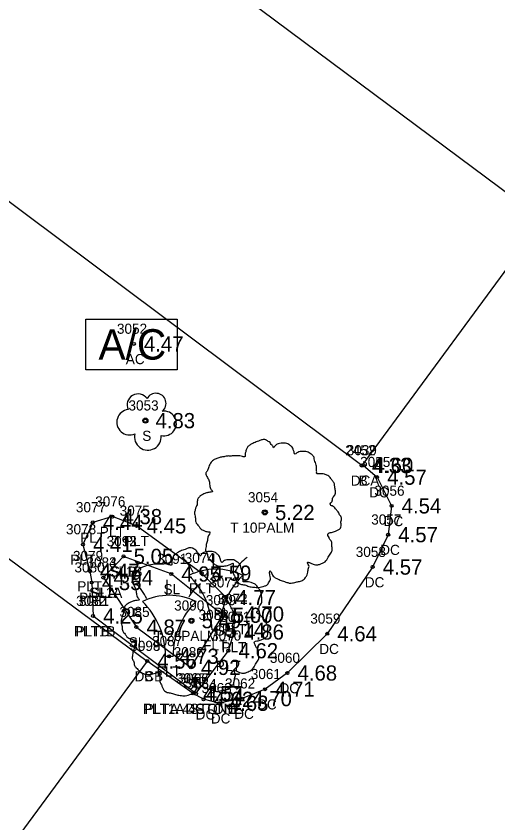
# Model space of a CAD drawing. Extents: x 2608598 to 2610682, y 641451 to 643526.
# Drawn here: x 2609965.9 to 2610013.4, y 642071.3 to 642151 of the extents above; entities that cross this region are included whole.
import ezdxf

# ---------------------------------------------------------------- set-up
doc = ezdxf.new("R2010")
doc.units = 0
for name, color, linetype in [('RD_EX_Bldg', 7, 'Continuous'), ('RD_EX_Bldg_txCode', 7, 'Continuous'), ('RD_EX_BldgApp', 7, 'Continuous'), ('RD_EX_BldgApp_txCode', 7, 'Continuous'), ('RD_EX_Conc', 7, 'Continuous'), ('RD_EX_Conc_txCode', 7, 'Continuous'), ('RD_EX_TX_Bldg_ELEV', 7, 'Continuous'), ('RD_EX_TX_BldgApp_ELEV', 7, 'Continuous'), ('RD_EX_TX_Conc_ELEV', 7, 'Continuous'), ('RD_EX_TX_VEG_ELEV', 7, 'Continuous'), ('RD_EX_VEG', 7, 'Continuous'), ('RD_EX_VEG_txCode', 7, 'Continuous'), ('RD_SMD_Locator', 7, 'Continuous')]:
    doc.layers.add(name, color=color, linetype=linetype)

msp = doc.modelspace()

# ---------------------------------------------------------------- linework, layer by layer
at = {"layer": 'RD_EX_Bldg'}
for points in [[(2609946.85, 642146.346), (2609965.057, 642170.243), (2610017.876, 642130.878), (2610000.016, 642106.607), (2609946.85, 642146.346)], [(2609925.869, 642126.537), (2609978.853, 642087.305), (2609961.016, 642063.114), (2609908.032, 642102.345), (2609925.869, 642126.537)]]:
    msp.add_lwpolyline(points, dxfattribs=at)
at = {"layer": 'RD_EX_BldgApp'}
for p, q in [((2609983.661, 642084.088), (2609973.511, 642091.75)), ((2609985.248, 642090.378), (2609985.998, 642090.378)), ((2609980.658, 642087.798), (2609981.408, 642087.798))]:
    msp.add_line(p, q, dxfattribs=at)
msp.add_lwpolyline([(2609972.804, 642116.056), (2609972.804, 642121.056), (2609981.804, 642121.056), (2609981.804, 642116.056)], close=True, dxfattribs=at)
msp.add_lwpolyline([(2609983.661, 642084.088), (2609986.863, 642088.328), (2609987.438, 642090.174), (2609987.45, 642091.947), (2609986.646, 642093.573), (2609984.226, 642095.984), (2609977.805, 642100.65), (2609975.417, 642101.56), (2609973.488, 642100.991), (2609972.51, 642098.817), (2609973.198, 642096.178), (2609973.385, 642095.054), (2609973.511, 642091.75)], dxfattribs=at)
for centre, radius, start, end in [((2609978.931, 642094.021), 4.895, 24.32791, 46.26654), ((2609947.542, 642097.716), 37.876, 358.06712, 0.27154), ((2609990.511, 642094.772), 3.283, 123.29064, 154.48862), ((2609985.623, 642090.378), 5.997, 63.77943, 116.22057), ((2609977.748, 642090.378), 7.5, 0, 45.83662), ((2609993.498, 642090.378), 7.5, 134.16338, 180), ((2609974.341, 642091.44), 4.895, 24.32791, 46.26654), ((2609942.952, 642095.135), 37.876, 358.06712, 0.27154), ((2609985.922, 642092.191), 3.283, 123.29064, 154.48862), ((2609981.033, 642087.798), 5.997, 63.77943, 116.22057), ((2609973.158, 642087.798), 7.5, 0, 45.83662), ((2609988.908, 642087.798), 7.5, 134.16338, 180)]:
    msp.add_arc(centre, radius, start, end, dxfattribs=at)
at = {"layer": 'RD_EX_Conc'}
msp.add_lwpolyline([(2610000.202, 642106.619), (2610001.534, 642105.457), (2610002.96, 642102.62), (2610002.625, 642099.778), (2610001.097, 642096.583), (2609996.612, 642089.998), (2609992.685, 642086.129), (2609990.483, 642084.529), (2609988.224, 642083.597), (2609985.911, 642083.142), (2609984.416, 642083.531), (2609983.386, 642084.107), (2609978.853, 642087.305)], dxfattribs=at)
at = {"layer": 'RD_EX_VEG'}
msp.add_line((2609974.531, 642095.545), (2609976.518, 642097.638), dxfattribs=at)
msp.add_lwpolyline([(2609974.531, 642095.545), (2609977.785, 642090.655), (2609983.161, 642086.682), (2609986.308, 642091.823), (2609981.222, 642095.898), (2609976.518, 642097.638)], dxfattribs=at)
for centre, radius in [((2609978.674, 642111.034), 0.25), ((2609990.462, 642101.972), 0.25), ((2609990.449, 642101.953), 0.0001), ((2609983.22, 642091.29), 0.25), ((2609983.208, 642091.271), 0.0001)]:
    msp.add_circle(centre, radius, dxfattribs=at)
for centre, radius, start, end in [((2609977.953, 642112.581), 1.084, 34.97629, 204.75602), ((2609979.719, 642112.736), 0.995, 308.76261, 152.04674), ((2609977.11, 642110.878), 1.257, 96.45179, 294.73401), ((2609980.514, 642110.754), 1.218, 256.56668, 98.10463), ((2609978.92, 642109.437), 1.318, 166.88266, 5.75893)]:
    msp.add_arc(centre, radius, start, end, dxfattribs=at)
for points in [[(2609990.594, 642109.139), (2609990.294, 642109.164), (2609989.969, 642109.064), (2609989.719, 642108.964), (2609989.494, 642108.889), (2609989.269, 642108.789), (2609988.97, 642108.615), (2609988.745, 642108.414), (2609988.62, 642108.165), (2609988.57, 642107.94), (2609988.52, 642107.665), (2609988.52, 642107.49), (2609988.395, 642107.465), (2609988.245, 642107.49), (2609987.995, 642107.565), (2609987.745, 642107.565), (2609987.495, 642107.565), (2609987.145, 642107.54), (2609986.795, 642107.54), (2609986.521, 642107.49), (2609986.196, 642107.44), (2609985.821, 642107.315), (2609985.471, 642107.19), (2609985.171, 642106.94), (2609984.921, 642106.465), (2609984.796, 642106.116), (2609984.646, 642105.866), (2609984.796, 642105.416), (2609984.971, 642105.066), (2609984.996, 642104.866), (2609985.071, 642104.441), (2609985.171, 642104.216), (2609985.296, 642104.016), (2609985.221, 642103.992), (2609984.846, 642103.941), (2609984.546, 642103.842), (2609984.122, 642103.617), (2609983.897, 642103.392), (2609983.797, 642103.067), (2609983.772, 642102.717), (2609983.672, 642102.517), (2609983.597, 642102.242), (2609983.572, 642102.167), (2609983.522, 642101.842), (2609983.622, 642101.393), (2609983.647, 642101.043), (2609983.772, 642100.818), (2609983.922, 642100.643), (2609984.097, 642100.393), (2609984.496, 642100.168), (2609984.821, 642100.068), (2609985.021, 642100.043), (2609984.846, 642099.543), (2609984.796, 642099.194), (2609984.671, 642098.794), (2609984.671, 642098.719), (2609984.621, 642098.244), (2609984.771, 642097.919), (2609984.846, 642097.544), (2609985.021, 642097.319), (2609985.296, 642097.02), (2609985.621, 642096.795), (2609986.121, 642096.67), (2609986.521, 642096.695), (2609987.095, 642096.87), (2609987.345, 642096.945), (2609987.32, 642096.77), (2609987.345, 642096.395), (2609987.345, 642095.97), (2609987.495, 642095.645), (2609987.595, 642095.37), (2609987.745, 642095.12), (2609988.07, 642094.895), (2609988.47, 642094.821), (2609988.895, 642094.671), (2609989.344, 642094.596), (2609989.844, 642094.571), (2609990.444, 642094.721), (2609990.719, 642094.846), (2609990.819, 642095.02), (2609991.019, 642095.395), (2609990.969, 642095.62), (2609990.994, 642096.22), (2609991.094, 642096.045), (2609991.269, 642095.695), (2609991.768, 642095.395), (2609992.168, 642095.22), (2609992.643, 642095.07), (2609992.943, 642094.995), (2609993.418, 642095.07), (2609993.792, 642095.145), (2609994.167, 642095.27), (2609994.467, 642095.545), (2609994.642, 642095.82), (2609994.692, 642096.095), (2609994.767, 642096.47), (2609994.817, 642096.645)], [(2609994.817, 642096.645), (2609994.742, 642096.82), (2609994.692, 642097.069), (2609994.767, 642097.044), (2609994.942, 642096.995), (2609995.217, 642096.87), (2609995.442, 642096.795), (2609995.767, 642096.82), (2609996.041, 642096.92), (2609996.491, 642097.194), (2609996.766, 642097.669), (2609997.041, 642098.069), (2609997.116, 642098.394), (2609997.066, 642098.619), (2609997.041, 642099.119), (2609996.841, 642099.368), (2609996.791, 642099.493), (2609996.691, 642099.893), (2609996.766, 642099.943), (2609997.041, 642099.993), (2609997.416, 642100.118), (2609997.691, 642100.243), (2609997.916, 642100.418), (2609997.991, 642100.643), (2609997.966, 642101.043), (2609998.016, 642101.443), (2609997.941, 642101.593), (2609997.841, 642101.742), (2609997.766, 642101.942), (2609997.616, 642102.092), (2609997.516, 642102.242), (2609997.416, 642102.342), (2609997.291, 642102.492), (2609997.116, 642102.617), (2609996.966, 642102.667), (2609996.916, 642102.817), (2609997.066, 642103.017), (2609997.116, 642103.117), (2609997.141, 642103.342), (2609997.366, 642103.692), (2609997.416, 642104.091), (2609997.366, 642104.516), (2609997.316, 642104.791), (2609997.166, 642105.066), (2609996.966, 642105.316), (2609996.841, 642105.491), (2609996.666, 642105.616), (2609996.341, 642105.741), (2609996.091, 642105.791), (2609995.742, 642105.791), (2609995.542, 642105.841), (2609995.567, 642105.891), (2609995.567, 642106.041), (2609995.567, 642106.316), (2609995.492, 642106.765), (2609995.342, 642107.265), (2609995.342, 642107.29), (2609995.242, 642107.54), (2609995.017, 642107.74), (2609994.842, 642107.84), (2609994.642, 642107.965), (2609994.392, 642107.99), (2609994.092, 642107.99), (2609993.817, 642107.94), (2609993.617, 642107.84), (2609993.443, 642107.715), (2609993.368, 642107.865), (2609993.268, 642108.165), (2609993.218, 642108.315), (2609993.068, 642108.49), (2609992.843, 642108.689), (2609992.393, 642108.814), (2609991.768, 642108.739), (2609991.468, 642108.539), (2609991.318, 642108.365), (2609991.269, 642108.49), (2609991.069, 642108.689), (2609990.969, 642108.864), (2609990.794, 642108.989), (2609990.644, 642109.089), (2609990.544, 642109.139)], [(2609983.352, 642098.457), (2609983.052, 642098.482), (2609982.728, 642098.382), (2609982.478, 642098.282), (2609982.253, 642098.207), (2609982.028, 642098.107), (2609981.728, 642097.933), (2609981.503, 642097.733), (2609981.378, 642097.483), (2609981.328, 642097.258), (2609981.278, 642096.983), (2609981.278, 642096.808), (2609981.153, 642096.783), (2609981.003, 642096.808), (2609980.753, 642096.883), (2609980.504, 642096.883), (2609980.254, 642096.883), (2609979.904, 642096.858), (2609979.554, 642096.858), (2609979.279, 642096.808), (2609978.954, 642096.758), (2609978.579, 642096.633), (2609978.23, 642096.508), (2609977.93, 642096.258), (2609977.68, 642095.784), (2609977.555, 642095.434), (2609977.405, 642095.184), (2609977.555, 642094.734), (2609977.73, 642094.384), (2609977.755, 642094.184), (2609977.83, 642093.759), (2609977.93, 642093.535), (2609978.055, 642093.335), (2609977.98, 642093.31), (2609977.605, 642093.26), (2609977.305, 642093.16), (2609976.88, 642092.935), (2609976.655, 642092.71), (2609976.555, 642092.385), (2609976.53, 642092.035), (2609976.43, 642091.835), (2609976.355, 642091.56), (2609976.33, 642091.485), (2609976.28, 642091.161), (2609976.38, 642090.711), (2609976.405, 642090.361), (2609976.53, 642090.136), (2609976.68, 642089.961), (2609976.855, 642089.711), (2609977.255, 642089.486), (2609977.58, 642089.386), (2609977.78, 642089.361), (2609977.605, 642088.862), (2609977.555, 642088.512), (2609977.43, 642088.112), (2609977.43, 642088.037), (2609977.38, 642087.562), (2609977.53, 642087.237), (2609977.605, 642086.862), (2609977.78, 642086.638), (2609978.055, 642086.338), (2609978.379, 642086.113), (2609978.879, 642085.988), (2609979.279, 642086.013), (2609979.854, 642086.188), (2609980.104, 642086.263), (2609980.079, 642086.088), (2609980.104, 642085.713), (2609980.104, 642085.288), (2609980.254, 642084.963), (2609980.354, 642084.688), (2609980.504, 642084.438), (2609980.828, 642084.214), (2609981.228, 642084.139), (2609981.653, 642083.989), (2609982.103, 642083.914), (2609982.603, 642083.889), (2609983.202, 642084.039), (2609983.477, 642084.164), (2609983.577, 642084.339), (2609983.777, 642084.713), (2609983.727, 642084.938), (2609983.752, 642085.538), (2609983.852, 642085.363), (2609984.027, 642085.013), (2609984.527, 642084.713), (2609984.927, 642084.538), (2609985.401, 642084.388), (2609985.701, 642084.314), (2609986.176, 642084.388), (2609986.551, 642084.463), (2609986.926, 642084.588), (2609987.226, 642084.863), (2609987.401, 642085.138), (2609987.451, 642085.413), (2609987.525, 642085.788), (2609987.575, 642085.963)], [(2609987.575, 642085.963), (2609987.501, 642086.138), (2609987.451, 642086.388), (2609987.525, 642086.363), (2609987.7, 642086.313), (2609987.975, 642086.188), (2609988.2, 642086.113), (2609988.525, 642086.138), (2609988.8, 642086.238), (2609989.25, 642086.513), (2609989.525, 642086.987), (2609989.799, 642087.387), (2609989.874, 642087.712), (2609989.824, 642087.937), (2609989.799, 642088.437), (2609989.6, 642088.687), (2609989.55, 642088.812), (2609989.45, 642089.211), (2609989.525, 642089.261), (2609989.799, 642089.311), (2609990.174, 642089.436), (2609990.449, 642089.561), (2609990.674, 642089.736), (2609990.749, 642089.961), (2609990.724, 642090.361), (2609990.774, 642090.761), (2609990.699, 642090.911), (2609990.599, 642091.061), (2609990.524, 642091.261), (2609990.374, 642091.41), (2609990.274, 642091.56), (2609990.174, 642091.66), (2609990.049, 642091.81), (2609989.874, 642091.935), (2609989.725, 642091.985), (2609989.675, 642092.135), (2609989.824, 642092.335), (2609989.874, 642092.435), (2609989.899, 642092.66), (2609990.124, 642093.01), (2609990.174, 642093.41), (2609990.124, 642093.834), (2609990.074, 642094.109), (2609989.924, 642094.384), (2609989.725, 642094.634), (2609989.6, 642094.809), (2609989.425, 642094.934), (2609989.1, 642095.059), (2609988.85, 642095.109), (2609988.5, 642095.109), (2609988.3, 642095.159), (2609988.325, 642095.209), (2609988.325, 642095.359), (2609988.325, 642095.634), (2609988.25, 642096.083), (2609988.1, 642096.583), (2609988.1, 642096.608), (2609988, 642096.858), (2609987.775, 642097.058), (2609987.6, 642097.158), (2609987.401, 642097.283), (2609987.151, 642097.308), (2609986.851, 642097.308), (2609986.576, 642097.258), (2609986.376, 642097.158), (2609986.201, 642097.033), (2609986.126, 642097.183), (2609986.026, 642097.483), (2609985.976, 642097.633), (2609985.826, 642097.808), (2609985.601, 642098.008), (2609985.151, 642098.132), (2609984.527, 642098.058), (2609984.227, 642097.858), (2609984.077, 642097.683), (2609984.027, 642097.808), (2609983.827, 642098.008), (2609983.727, 642098.182), (2609983.552, 642098.307), (2609983.402, 642098.407), (2609983.302, 642098.457)]]:
    msp.add_spline(points, degree=3, dxfattribs=at)
at = {"layer": 'RD_SMD_Locator'}
for centre in [(2609977.538, 642118.607), (2609978.674, 642111.034), (2610000.016, 642106.607), (2610000.202, 642106.619), (2610001.534, 642105.457), (2609990.462, 642101.972), (2610002.96, 642102.62), (2609975.417, 642101.56), (2609973.488, 642100.991), (2609977.805, 642100.65), (2610002.625, 642099.778), (2609972.51, 642098.817), (2609976.518, 642097.638), (2609976.518, 642097.638), (2610001.097, 642096.583), (2609973.198, 642096.178), (2609974.531, 642095.545), (2609974.531, 642095.545), (2609981.222, 642095.898), (2609984.226, 642095.984), (2609973.385, 642095.054), (2609986.646, 642093.573), (2609973.511, 642091.75), (2609973.511, 642091.75), (2609986.308, 642091.823), (2609987.45, 642091.947), (2609983.22, 642091.29), (2609977.785, 642090.655), (2609985.595, 642090.36), (2609987.438, 642090.174), (2609996.612, 642089.998), (2609981.006, 642087.779), (2609986.863, 642088.328), (2609978.853, 642087.305), (2609978.853, 642087.305), (2609983.161, 642086.682), (2609992.685, 642086.129), (2609990.483, 642084.529), (2609983.386, 642084.107), (2609983.661, 642084.088), (2609983.661, 642084.088), (2609988.224, 642083.597), (2609984.416, 642083.531), (2609985.911, 642083.142)]:
    msp.add_circle(centre, 0.15, dxfattribs=at)

# ---------------------------------------------------------------- texts
at = {"layer": 'RD_EX_Bldg_txCode'}
for s, p in [('2452', (2609998.386, 642107.607)), ('B', (2609999.709, 642104.607)), ('3099', (2609977.184, 642088.305)), ('B', (2609978.546, 642085.305))]:
    msp.add_text(s, height=1, dxfattribs=at).set_placement(p)
at = {"layer": 'RD_EX_BldgApp'}
msp.add_text('A/C', height=3, dxfattribs=at).set_placement((2609974.05, 642117.059))
at = {"layer": 'RD_EX_BldgApp_txCode'}
for s, p in [('3052', (2609975.869, 642119.607)), ('AC', (2609976.743, 642116.607)), ('3077', (2609971.819, 642101.991)), ('3076', (2609973.724, 642102.56)), ('3075', (2609976.136, 642101.65)), ('3078', (2609970.841, 642099.817)), ('PLT', (2609974.173, 642099.56)), ('PLT', (2609972.244, 642098.991)), ('PLT', (2609976.561, 642098.65)), ('3079', (2609971.529, 642097.178)), ('PLT', (2609971.266, 642096.817)), ('3074', (2609982.557, 642096.984)), ('3080', (2609971.677, 642096.054)), ('PLT', (2609971.954, 642094.178)), ('PLT', (2609982.982, 642093.984)), ('3073', (2609984.977, 642094.573)), ('PLT', (2609972.141, 642093.054)), ('3082', (2609971.842, 642092.75)), ('3081', (2609972.125, 642092.75)), ('3072', (2609985.781, 642092.947)), ('PLT', (2609985.402, 642091.573)), ('3088', (2609983.926, 642091.36)), ('3071', (2609986.052, 642091.174)), ('PLT', (2609986.206, 642089.947)), ('PLT1B', (2609971.629, 642089.75)), ('PLTB', (2609971.795, 642089.75)), ('3070', (2609985.154, 642089.328)), ('3087', (2609979.336, 642088.779)), ('FLT', (2609984.375, 642088.36)), ('PLT', (2609986.194, 642088.174)), ('PLT', (2609985.619, 642086.328)), ('FLT', (2609979.785, 642085.779)), ('3066', (2609981.944, 642085.088)), ('3067', (2609981.968, 642085.088)), ('PLT1A 4STONE', (2609978.436, 642082.088)), ('PLTA 4STONE', (2609978.602, 642082.088))]:
    msp.add_text(s, height=1, dxfattribs=at).set_placement(p)
at = {"layer": 'RD_EX_Conc_txCode'}
for s, p in [('3039', (2609998.533, 642107.619)), ('3055', (2609999.865, 642106.457)), ('DCA', (2609998.935, 642104.619)), ('DC', (2610000.754, 642103.457)), ('3056', (2610001.267, 642103.62)), ('3057', (2610000.955, 642100.778)), ('DC', (2610002.18, 642100.62)), ('3058', (2609999.428, 642097.583)), ('DC', (2610001.845, 642097.778)), ('DC', (2610000.318, 642094.583)), ('3059', (2609994.943, 642090.998)), ('3098', (2609977.184, 642088.305)), ('DC', (2609995.833, 642087.998)), ('3060', (2609990.952, 642087.129)), ('DCB', (2609977.601, 642085.305)), ('3065', (2609981.693, 642085.107)), ('3061', (2609989.074, 642085.529)), ('3064', (2609982.723, 642084.531)), ('3062', (2609986.531, 642084.597)), ('3063', (2609984.218, 642084.142)), ('DC', (2609991.905, 642084.129)), ('DC', (2609982.606, 642082.107)), ('DC', (2609989.704, 642082.529)), ('DC', (2609983.636, 642081.531)), ('DC', (2609985.131, 642081.142)), ('DC', (2609987.444, 642081.597))]:
    msp.add_text(s, height=1, dxfattribs=at).set_placement(p)
at = {"layer": 'RD_EX_TX_Bldg_ELEV'}
for s, p in [('4.33', (2610001.016, 642105.857)), ('4.56', (2609979.853, 642086.555))]:
    msp.add_text(s, height=1.5, dxfattribs=at).set_placement(p)
at = {"layer": 'RD_EX_TX_BldgApp_ELEV'}
for s, p in [('4.47', (2609978.538, 642117.857)), ('4.38', (2609976.417, 642100.81)), ('4.44', (2609974.488, 642100.241)), ('4.45', (2609978.805, 642099.9)), ('4.41', (2609973.51, 642098.067)), ('4.47', (2609974.198, 642095.428)), ('4.59', (2609985.226, 642095.234)), ('4.35', (2609974.385, 642094.304)), ('4.77', (2609987.646, 642092.823)), ('4.25', (2609974.511, 642091)), ('4.25', (2609974.511, 642091)), ('4.70', (2609988.45, 642091.197)), ('5.14', (2609986.595, 642089.61)), ('4.86', (2609988.438, 642089.424)), ('4.73', (2609982.006, 642087.029)), ('4.62', (2609987.863, 642087.578)), ('4.51', (2609984.661, 642083.338)), ('4.51', (2609984.661, 642083.338))]:
    msp.add_text(s, height=1.5, dxfattribs=at).set_placement(p)
at = {"layer": 'RD_EX_TX_Conc_ELEV'}
for s, p in [('4.60', (2610001.202, 642105.869)), ('4.57', (2610002.534, 642104.707)), ('4.54', (2610003.96, 642101.87)), ('4.57', (2610003.625, 642099.028)), ('4.57', (2610002.097, 642095.833)), ('4.64', (2609997.612, 642089.248)), ('4.56', (2609979.853, 642086.555)), ('4.68', (2609993.685, 642085.379)), ('4.57', (2609984.386, 642083.357)), ('4.71', (2609991.483, 642083.779)), ('4.62', (2609985.416, 642082.781)), ('4.63', (2609986.911, 642082.392)), ('4.70', (2609989.224, 642082.847))]:
    msp.add_text(s, height=1.5, dxfattribs=at).set_placement(p)
at = {"layer": 'RD_EX_TX_VEG_ELEV'}
for s, p in [('4.83', (2609979.674, 642110.284)), ('5.22', (2609991.462, 642101.222)), ('5.05', (2609977.518, 642096.888)), ('5.05', (2609977.518, 642096.888)), ('4.95', (2609982.222, 642095.148)), ('4.94', (2609975.531, 642094.795)), ('4.94', (2609975.531, 642094.795)), ('5.00', (2609987.308, 642091.073)), ('5.49', (2609984.22, 642090.54)), ('4.87', (2609978.785, 642089.905)), ('4.92', (2609984.161, 642085.932))]:
    msp.add_text(s, height=1.5, dxfattribs=at).set_placement(p)
at = {"layer": 'RD_EX_VEG_txCode'}
for s, p in [('3053', (2609977.005, 642112.034)), ('S', (2609978.367, 642109.034)), ('3054', (2609988.793, 642102.972)), ('T 10PALM', (2609987.052, 642099.972)), ('3092', (2609974.849, 642098.638)), ('3093', (2609974.849, 642098.638)), ('3083', (2609972.862, 642096.545)), ('3084', (2609972.862, 642096.545)), ('3091', (2609979.836, 642096.898)), ('SL1B', (2609975.124, 642095.638)), ('SLB', (2609975.29, 642095.638)), ('SL', (2609980.466, 642093.898)), ('SL1A', (2609973.122, 642093.545)), ('SLA', (2609973.287, 642093.545)), ('3090', (2609981.512, 642092.29)), ('3089', (2609984.639, 642092.823)), ('3085', (2609976.115, 642091.655)), ('T 26PALM', (2609979.543, 642089.29)), ('SL', (2609985.552, 642089.823)), ('SL', (2609977.029, 642088.655)), ('3086', (2609981.468, 642087.682)), ('SL', (2609982.405, 642084.682))]:
    msp.add_text(s, height=1, dxfattribs=at).set_placement(p)

doc.saveas('drawing.dxf')
